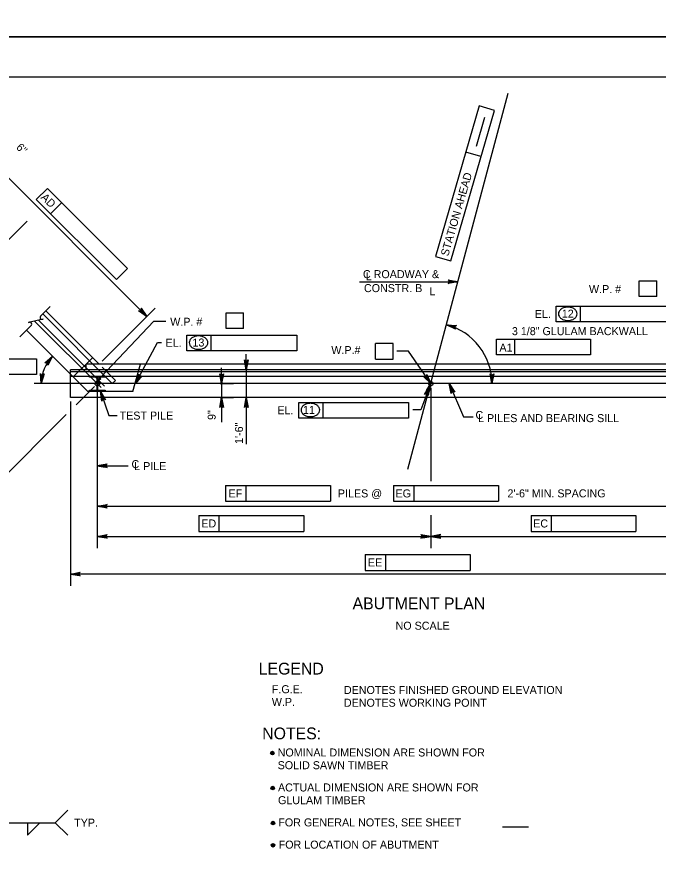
# Model space of a CAD drawing. Extents: x 638304 to 640306, y 296653 to 298435.
# Drawn here: x 639453.1 to 639693.3, y 296941.8 to 297255 of the extents above; entities that cross this region are included whole.
import ezdxf

# ---------------------------------------------------------------- set-up
doc = ezdxf.new("R2010")
doc.units = 0
for name, color, linetype in [('2', 7, 'Continuous'), ('3', 7, 'Continuous'), ('4', 7, 'Continuous'), ('5', 7, 'Continuous'), ('Level 2', 7, 'Continuous'), ('Level 3', 7, 'Continuous'), ('Level 4', 7, 'Continuous'), ('Level 5', 7, 'Continuous'), ('Level 6', 7, 'Continuous'), ('Level 8', 7, 'Continuous'), ('PLT-BNDY', 7, 'Continuous')]:
    doc.layers.add(name, color=color, linetype=linetype)

# ---------------------------------------------------------------- blocks, each defined once
blk = doc.blocks.new('HPILE')
at = {"layer": '3'}
for p, q in [((-0.12, -2.66), (-0.12, 2.66)), ((0.12, 2.66), (0.12, -2.66)), ((-3.67, -3.1), (-0.56, -3.1))]:
    blk.add_line(p, q, dxfattribs=at)
for points in [[(-0.56, 3.1), (-3.67, 3.1), (-3.67, 3.54), (3.67, 3.54), (3.67, 3.1), (0.56, 3.1)], [(0.56, -3.1), (3.67, -3.1), (3.67, -3.54), (-3.67, -3.54), (-3.67, -3.1)]]:
    blk.add_lwpolyline(points, dxfattribs=at)
for centre, start, end in [((-0.56, 2.66), 0, 90), ((0.56, 2.66), 90, 180), ((-0.56, -2.66), 270, 0), ((0.56, -2.66), 180, 270)]:
    blk.add_arc(centre, 0.438, start, end, dxfattribs=at)

msp = doc.modelspace()

# ---------------------------------------------------------------- linework, layer by layer
at = {"layer": '2'}
msp.add_line((639316.46, 297232.46), (640102.46, 297232.46), dxfattribs=at)
at = {"layer": 'Level 2'}
for p, q in [((639483.96, 297124.79), (639464, 297144.75)), ((639479.69, 297114.48), (639456.71, 297137.46)), ((639481.53, 297127.23), (639474.24, 297119.93)), ((639730.06, 297124.79), (639483.96, 297124.79)), ((639496.59, 297114.48), (639499.34, 297124.79)), ((639473.15, 297112.27), (639473.15, 297121.02)), ((639488.84, 297117.43), (639490.06, 297118.64)), ((639496.59, 297114.48), (639479.69, 297114.48)), ((639742.02, 297112.27), (639473.15, 297112.27))]:
    msp.add_line(p, q, dxfattribs=at)
at = {"layer": 'Level 3'}
for p, q in [((639488.84, 297117.43), (639462.79, 297143.54)), ((639473.15, 297121.02), (639473.15, 297122.58)), ((639742.02, 297122.58), (639473.15, 297122.58)), ((639479.08, 297122.58), (639479.08, 297124.79)), ((639483.96, 297124.79), (639479.08, 297124.79)), ((639485.11, 297123.65), (639490.06, 297118.64)), ((639473.15, 297121.93), (639742.02, 297121.93)), ((639473.15, 297120.21), (639742.02, 297120.21)), ((639467.49, 296952.85), (639472.19, 296957.55)), ((639437.91, 296952.85), (639467.49, 296952.85)), ((639457.06, 296952.85), (639457.06, 296948.15)), ((639457.06, 296948.15), (639461.75, 296952.85)), ((639467.49, 296952.85), (639472.19, 296948.15))]:
    msp.add_line(p, q, dxfattribs=at)
msp.add_circle((639608.09, 297117.43), 0.849, dxfattribs=at)
at = {"layer": 'Level 4'}
for p, q in [((639626.25, 297221.5), (639609.92, 297165.05)), ((639615.58, 297163.41), (639631.91, 297219.86)), ((639631.91, 297219.86), (639626.25, 297221.5)), ((639628.25, 297217.17), (639625.11, 297206.31)), ((639626.9, 297202.53), (639621.24, 297204.17)), ((639501.81, 297142.64), (639442.58, 297201.87)), ((639464.55, 297190.63), (639460.38, 297186.46)), ((639464.55, 297190.63), (639494.56, 297160.62)), ((639460.38, 297186.46), (639490.39, 297156.46)), ((639469.89, 297185.3), (639465.72, 297181.13)), ((639443.68, 297165.07), (639456.96, 297178.35)), ((639609.92, 297165.05), (639615.58, 297163.41)), ((639494.56, 297160.62), (639490.39, 297156.46)), ((639581.37, 297155.63), (639618.28, 297155.63)), ((639686.1, 297150.08), (639686.1, 297155.97)), ((639686.1, 297155.97), (639692.68, 297155.97)), ((639692.68, 297150.08), (639692.68, 297155.97)), ((639692.68, 297150.08), (639686.1, 297150.08)), ((639485.05, 297125.88), (639504.94, 297145.77)), ((639531.44, 297144), (639538.02, 297144)), ((639531.44, 297138.1), (639531.44, 297144)), ((639538.02, 297138.1), (639538.02, 297144)), ((639655.04, 297146.46), (639696.17, 297146.46)), ((639655.04, 297140.56), (639655.04, 297146.46)), ((639664.19, 297140.56), (639664.19, 297146.46)), ((639484.65, 297116), (639459.76, 297140.89)), ((639485.87, 297116.52), (639461.18, 297141.21)), ((639538.02, 297138.1), (639531.44, 297138.1)), ((639696.17, 297140.56), (639655.04, 297140.56)), ((639485.05, 297125.88), (639496.73, 297137.56)), ((639516.76, 297135.64), (639557.89, 297135.64)), ((639516.76, 297129.75), (639516.76, 297135.64)), ((639525.91, 297129.75), (639525.91, 297135.64)), ((639557.89, 297135.64), (639557.89, 297129.75)), ((639497.49, 297117.43), (639505.72, 297132.86)), ((639505.72, 297132.86), (639507.31, 297132.86)), ((639593.99, 297132.49), (639587.41, 297132.49)), ((639587.41, 297126.6), (639587.41, 297132.49)), ((639593.99, 297126.6), (639593.99, 297132.49)), ((639632.71, 297134.11), (639667.94, 297134.11)), ((639632.71, 297128.22), (639632.71, 297134.11)), ((639639.54, 297128.22), (639639.54, 297134.11)), ((639667.94, 297134.11), (639667.94, 297128.22)), ((639557.89, 297129.75), (639516.76, 297129.75)), ((639539.02, 297125.53), (639539.02, 297128.48)), ((639425.25, 297126.72), (639460.48, 297126.72)), ((639460.48, 297126.72), (639460.48, 297120.83)), ((639587.41, 297126.6), (639593.99, 297126.6)), ((639667.94, 297128.22), (639632.71, 297128.22)), ((639529.75, 297120.37), (639529.75, 297123.32)), ((639538.45, 297122.58), (639534.6, 297122.58)), ((639539.02, 297122.58), (639539.02, 297112.27)), ((639460.48, 297120.83), (639425.25, 297120.83)), ((639754.22, 297117.43), (639459.61, 297117.43)), ((639482.14, 297116.34), (639475.28, 297109.48)), ((639483.23, 297115.89), (639483.23, 297055.75)), ((639529.25, 297117.43), (639534.17, 297117.43)), ((639529.75, 297117.43), (639529.75, 297112.27)), ((639607.72, 297116.66), (639604.35, 297107.62)), ((639608.09, 297115.89), (639608.09, 297080.88)), ((639473.15, 297110.73), (639473.15, 297041.63)), ((639529.25, 297112.27), (639534.17, 297112.27)), ((639538.45, 297112.27), (639534.6, 297112.27)), ((639558.66, 297110.4), (639599.79, 297110.4)), ((639558.66, 297104.51), (639558.66, 297110.4)), ((639567.81, 297104.51), (639567.81, 297110.4)), ((639599.79, 297110.4), (639599.79, 297104.51)), ((639529.75, 297109.32), (639529.75, 297103.04)), ((639539.02, 297109.32), (639539.02, 297094.76)), ((639604.35, 297107.62), (639601.4, 297107.62)), ((639471.63, 297105.83), (639444.58, 297078.78)), ((639599.79, 297104.51), (639558.66, 297104.51)), ((639483.23, 297086.68), (639494.82, 297086.68)), ((639531.27, 297079.23), (639531.27, 297073.34)), ((639531.27, 297079.23), (639570.57, 297079.23)), ((639538.82, 297079.23), (639538.82, 297073.34)), ((639570.57, 297079.23), (639570.57, 297073.34)), ((639594.17, 297079.23), (639633.46, 297079.23)), ((639594.17, 297079.23), (639594.17, 297073.34)), ((639601.71, 297079.23), (639601.71, 297073.34)), ((639633.46, 297079.23), (639633.46, 297073.34)), ((639531.27, 297073.34), (639570.57, 297073.34)), ((639594.17, 297073.34), (639633.46, 297073.34)), ((639483.23, 297071.48), (639730.79, 297071.48)), ((639521.24, 297067.98), (639560.53, 297067.98)), ((639521.24, 297067.98), (639521.24, 297062.08)), ((639528.78, 297067.98), (639528.78, 297062.08)), ((639560.53, 297067.98), (639560.53, 297062.08)), ((639608.09, 297068.17), (639608.09, 297055.75)), ((639645.63, 297067.98), (639684.92, 297067.98)), ((639645.63, 297067.98), (639645.63, 297062.08)), ((639653.17, 297067.98), (639653.17, 297062.08)), ((639684.92, 297067.98), (639684.92, 297062.08)), ((639483.23, 297060.17), (639605.14, 297060.17)), ((639521.24, 297062.08), (639560.53, 297062.08)), ((639611.04, 297060.17), (639730.79, 297060.17)), ((639645.63, 297062.08), (639684.92, 297062.08)), ((639583.55, 297053.36), (639622.85, 297053.36)), ((639583.55, 297053.36), (639583.55, 297047.46)), ((639591.1, 297053.36), (639591.1, 297047.46)), ((639622.85, 297053.36), (639622.85, 297047.46)), ((639583.55, 297047.46), (639622.85, 297047.46)), ((639742.02, 297046.05), (639473.15, 297046.05)), ((639635.01, 296951.27), (639644.66, 296951.27))]:
    msp.add_line(p, q, dxfattribs=at)
for points in [[(639618.28, 297155.63), (639614.56, 297154.93), (639614.84, 297155.13), (639614.99, 297155.38), (639615.03, 297155.63), (639614.99, 297155.88), (639614.84, 297156.13), (639614.56, 297156.33), (639618.28, 297155.63), (639614.84, 297156.13), (639614.99, 297155.88), (639618.28, 297155.63), (639615.03, 297155.63), (639614.99, 297155.38), (639618.28, 297155.63), (639614.84, 297155.13)], [(639501.81, 297142.64), (639498.68, 297144.78), (639499.03, 297144.72), (639499.31, 297144.79), (639499.52, 297144.94), (639499.66, 297145.14), (639499.73, 297145.43), (639499.67, 297145.77), (639501.81, 297142.64), (639499.73, 297145.43), (639499.66, 297145.14), (639501.81, 297142.64), (639499.52, 297144.94), (639499.31, 297144.79), (639501.81, 297142.64), (639499.03, 297144.72)], [(639482.34, 297117.43), (639504.43, 297140.9), (639508.91, 297140.9)], [(639613.98, 297139.52), (639617.76, 297139.24), (639617.43, 297139.13), (639617.22, 297138.92), (639617.12, 297138.69), (639617.09, 297138.44), (639617.17, 297138.16), (639617.4, 297137.89), (639613.98, 297139.52), (639617.17, 297138.16), (639617.09, 297138.44), (639613.98, 297139.52), (639617.12, 297138.69), (639617.22, 297138.92), (639613.98, 297139.52), (639617.43, 297139.13)], [(639608.09, 297117.43), (639599.79, 297129.63), (639595.34, 297129.63)], [(639466.49, 297127.68), (639464.7, 297124.34), (639464.73, 297124.69), (639464.62, 297124.96), (639464.46, 297125.15), (639464.23, 297125.27), (639463.95, 297125.32), (639463.61, 297125.22), (639466.49, 297127.68), (639463.95, 297125.32), (639464.23, 297125.27), (639466.49, 297127.68), (639464.46, 297125.15), (639464.62, 297124.96), (639466.49, 297127.68), (639464.73, 297124.69)], [(639539.02, 297122.58), (639538.32, 297126.31), (639538.52, 297126.02), (639538.77, 297125.87), (639539.02, 297125.83), (639539.27, 297125.87), (639539.52, 297126.02), (639539.72, 297126.31), (639539.02, 297122.58), (639539.52, 297126.02), (639539.27, 297125.87), (639539.02, 297122.58), (639539.02, 297125.83), (639538.77, 297125.87), (639539.02, 297122.58), (639538.52, 297126.02)], [(639462.25, 297117.43), (639461.94, 297121.2), (639462.11, 297120.89), (639462.35, 297120.72), (639462.59, 297120.65), (639462.84, 297120.67), (639463.11, 297120.79), (639463.33, 297121.05), (639462.25, 297117.43), (639463.11, 297120.79), (639462.84, 297120.67), (639462.25, 297117.43), (639462.59, 297120.65), (639462.35, 297120.72), (639462.25, 297117.43), (639462.11, 297120.89)], [(639497.49, 297117.43), (639498.63, 297121.04), (639498.67, 297120.69), (639498.82, 297120.44), (639499.02, 297120.29), (639499.26, 297120.21), (639499.55, 297120.22), (639499.86, 297120.38), (639497.49, 297117.43), (639499.55, 297120.22), (639499.26, 297120.21), (639497.49, 297117.43), (639499.02, 297120.29), (639498.82, 297120.44), (639497.49, 297117.43), (639498.67, 297120.69)], [(639529.75, 297117.43), (639529.05, 297121.15), (639529.25, 297120.86), (639529.5, 297120.71), (639529.75, 297120.67), (639530, 297120.71), (639530.25, 297120.86), (639530.44, 297121.15), (639529.75, 297117.43), (639530.25, 297120.86), (639530, 297120.71), (639529.75, 297117.43), (639529.75, 297120.67), (639529.5, 297120.71), (639529.75, 297117.43), (639529.25, 297120.86)], [(639608.09, 297117.43), (639605.42, 297120.11), (639605.75, 297119.99), (639606.04, 297120), (639606.27, 297120.11), (639606.45, 297120.28), (639606.57, 297120.55), (639606.57, 297120.89), (639608.09, 297117.43), (639606.57, 297120.55), (639606.45, 297120.28), (639608.09, 297117.43), (639606.27, 297120.11), (639606.04, 297120), (639608.09, 297117.43), (639605.75, 297119.99)], [(639630.99, 297117.43), (639630.29, 297121.15), (639630.49, 297120.86), (639630.74, 297120.71), (639630.99, 297120.67), (639631.24, 297120.71), (639631.49, 297120.86), (639631.69, 297121.15), (639630.99, 297117.43), (639631.49, 297120.86), (639631.24, 297120.71), (639630.99, 297117.43), (639630.99, 297120.67), (639630.74, 297120.71), (639630.99, 297117.43), (639630.49, 297120.86)], [(639607.72, 297116.66), (639607.08, 297112.93), (639606.99, 297113.27), (639606.81, 297113.49), (639606.59, 297113.62), (639606.34, 297113.67), (639606.05, 297113.62), (639605.77, 297113.42), (639607.72, 297116.66), (639606.05, 297113.62), (639606.34, 297113.67), (639607.72, 297116.66), (639606.59, 297113.62), (639606.81, 297113.49), (639607.72, 297116.66), (639606.99, 297113.27)], [(639614.92, 297117.43), (639620.33, 297105), (639624.01, 297105)], [(639614.92, 297117.43), (639617.05, 297114.29), (639616.75, 297114.47), (639616.46, 297114.51), (639616.21, 297114.45), (639616, 297114.31), (639615.83, 297114.08), (639615.77, 297113.73), (639614.92, 297117.43), (639615.83, 297114.08), (639616, 297114.31), (639614.92, 297117.43), (639616.21, 297114.45), (639616.46, 297114.51), (639614.92, 297117.43), (639616.75, 297114.47)], [(639484.41, 297114.65), (639487.5, 297105.55), (639490.72, 297105.55)], [(639484.41, 297114.65), (639486.27, 297111.35), (639485.99, 297111.56), (639485.7, 297111.62), (639485.45, 297111.58), (639485.23, 297111.46), (639485.04, 297111.24), (639484.95, 297110.9), (639484.41, 297114.65), (639485.04, 297111.24), (639485.23, 297111.46), (639484.41, 297114.65), (639485.45, 297111.58), (639485.7, 297111.62), (639484.41, 297114.65), (639485.99, 297111.56)], [(639529.75, 297112.27), (639530.44, 297108.55), (639530.25, 297108.83), (639530, 297108.98), (639529.75, 297109.02), (639529.5, 297108.98), (639529.25, 297108.83), (639529.05, 297108.55), (639529.75, 297112.27), (639529.25, 297108.83), (639529.5, 297108.98), (639529.75, 297112.27), (639529.75, 297109.02), (639530, 297108.98), (639529.75, 297112.27), (639530.25, 297108.83)], [(639539.02, 297112.27), (639539.72, 297108.55), (639539.52, 297108.83), (639539.27, 297108.98), (639539.02, 297109.02), (639538.77, 297108.98), (639538.52, 297108.83), (639538.32, 297108.55), (639539.02, 297112.27), (639538.52, 297108.83), (639538.77, 297108.98), (639539.02, 297112.27), (639539.02, 297109.02), (639539.27, 297108.98), (639539.02, 297112.27), (639539.52, 297108.83)], [(639483.23, 297086.68), (639486.95, 297087.38), (639486.66, 297087.18), (639486.51, 297086.93), (639486.47, 297086.68), (639486.51, 297086.43), (639486.66, 297086.19), (639486.95, 297085.99), (639483.23, 297086.68), (639486.66, 297086.19), (639486.51, 297086.43), (639483.23, 297086.68), (639486.47, 297086.68), (639486.51, 297086.93), (639483.23, 297086.68), (639486.66, 297087.18)], [(639483.23, 297071.48), (639486.95, 297072.18), (639486.66, 297071.98), (639486.51, 297071.73), (639486.47, 297071.48), (639486.51, 297071.23), (639486.66, 297070.98), (639486.95, 297070.78), (639483.23, 297071.48), (639486.66, 297070.98), (639486.51, 297071.23), (639483.23, 297071.48), (639486.47, 297071.48), (639486.51, 297071.73), (639483.23, 297071.48), (639486.66, 297071.98)], [(639483.23, 297060.17), (639486.95, 297060.87), (639486.66, 297060.67), (639486.51, 297060.42), (639486.47, 297060.17), (639486.51, 297059.92), (639486.66, 297059.67), (639486.95, 297059.47), (639483.23, 297060.17), (639486.66, 297059.67), (639486.51, 297059.92), (639483.23, 297060.17), (639486.47, 297060.17), (639486.51, 297060.42), (639483.23, 297060.17), (639486.66, 297060.67)], [(639608.09, 297060.17), (639604.37, 297059.47), (639604.66, 297059.67), (639604.8, 297059.92), (639604.85, 297060.17), (639604.8, 297060.42), (639604.66, 297060.67), (639604.37, 297060.87), (639608.09, 297060.17), (639604.66, 297060.67), (639604.8, 297060.42), (639608.09, 297060.17), (639604.85, 297060.17), (639604.8, 297059.92), (639608.09, 297060.17), (639604.66, 297059.67)], [(639608.09, 297060.17), (639611.81, 297059.47), (639611.53, 297059.67), (639611.38, 297059.92), (639611.33, 297060.17), (639611.38, 297060.42), (639611.53, 297060.67), (639611.81, 297060.87), (639608.09, 297060.17), (639611.53, 297060.67), (639611.38, 297060.42), (639608.09, 297060.17), (639611.33, 297060.17), (639611.38, 297059.92), (639608.09, 297060.17), (639611.53, 297059.67)], [(639473.15, 297046.05), (639476.87, 297046.75), (639476.58, 297046.55), (639476.43, 297046.3), (639476.39, 297046.05), (639476.43, 297045.8), (639476.58, 297045.55), (639476.87, 297045.35), (639473.15, 297046.05), (639476.58, 297045.55), (639476.43, 297045.8), (639473.15, 297046.05), (639476.39, 297046.05), (639476.43, 297046.3), (639473.15, 297046.05), (639476.58, 297046.55)]]:
    msp.add_lwpolyline(points, dxfattribs=at)
for points in [[(639500.07, 297145.07), (639499.38, 297144.38), (639501.81, 297142.64)], [(639538.53, 297125.53), (639539.51, 297125.53), (639539.02, 297122.58)], [(639482.34, 297117.43), (639484.53, 297119.41), (639484.18, 297119.74)], [(639529.26, 297120.37), (639530.24, 297120.37), (639529.75, 297117.43)], [(639608.09, 297117.43), (639606.23, 297119.73), (639606.64, 297120)], [(639607.45, 297114.51), (639606.53, 297114.88), (639608.09, 297117.43)], [(639614.92, 297117.43), (639615.87, 297114.62), (639616.32, 297114.82)], [(639484.41, 297114.65), (639485.12, 297111.78), (639485.59, 297111.94)], [(639529.26, 297109.32), (639530.24, 297109.32), (639529.75, 297112.27)], [(639538.53, 297109.32), (639539.51, 297109.32), (639539.02, 297112.27)], [(639486.17, 297086.19), (639486.17, 297087.17), (639483.23, 297086.68)], [(639486.17, 297071.97), (639486.17, 297070.99), (639483.23, 297071.48)], [(639486.17, 297060.66), (639486.17, 297059.68), (639483.23, 297060.17)], [(639605.14, 297060.66), (639605.14, 297059.68), (639608.09, 297060.17)], [(639611.04, 297060.66), (639611.04, 297059.68), (639608.09, 297060.17)], [(639476.09, 297046.54), (639476.09, 297045.56), (639473.15, 297046.05)]]:
    msp.add_lwpolyline(points, close=True, dxfattribs=at)
for centre, radius in [((639483.23, 297117.43), 0.849), ((639548.78, 296978.97), 0.665), ((639548.78, 296978.97), 0.499), ((639548.78, 296978.97), 0.333), ((639548.78, 296978.97), 0.166), ((639548.91, 296965.87), 0.665), ((639548.91, 296965.87), 0.499), ((639548.91, 296965.87), 0.333), ((639548.91, 296965.87), 0.166), ((639549.03, 296952.76), 0.665), ((639549.03, 296952.76), 0.499), ((639549.03, 296952.76), 0.333), ((639549.03, 296952.76), 0.166), ((639549.03, 296944.4), 0.665), ((639549.03, 296944.4), 0.499), ((639549.03, 296944.4), 0.333), ((639549.03, 296944.4), 0.166)]:
    msp.add_circle(centre, radius, dxfattribs=at)
for centre, radius, start, end in [((639657.74, 297143.62), 1.82, 149.9767, 180), ((639658.54, 297143.15), 2.75, 125.6316, 149.9767), ((639659.07, 297142.42), 3.65, 106.5358, 125.6316), ((639659.41, 297141.26), 4.86, 90, 106.5358), ((639659.41, 297141.26), 4.86, 73.4642, 90), ((639659.75, 297142.42), 3.65, 54.3684, 73.4642), ((639660.28, 297143.15), 2.75, 30.0233, 54.3684), ((639661.08, 297143.62), 1.82, 0, 30.0233), ((639657.74, 297143.62), 1.82, 180, 210.0233), ((639658.54, 297144.08), 2.75, 210.0233, 234.3684), ((639659.07, 297144.81), 3.65, 234.3684, 253.4642), ((639659.41, 297145.97), 4.86, 253.4642, 270), ((639659.41, 297145.97), 4.86, 270, 286.5358), ((639659.75, 297144.81), 3.65, 286.5358, 305.6316), ((639660.28, 297144.08), 2.75, 305.6316, 329.9767), ((639661.08, 297143.62), 1.82, 329.9767, 0), ((639608.13, 297117.43), 22.86, 359.9991, 75.1778), ((639520.26, 297132.34), 2.75, 125.6316, 149.9767), ((639520.79, 297131.61), 3.65, 106.5358, 125.6316), ((639521.13, 297130.45), 4.86, 90, 106.5358), ((639521.13, 297130.45), 4.86, 73.4642, 90), ((639521.47, 297131.61), 3.65, 54.3684, 73.4642), ((639522, 297132.34), 2.75, 30.0233, 54.3684), ((639519.46, 297132.8), 1.82, 149.9767, 180), ((639519.46, 297132.8), 1.82, 180, 210.0233), ((639520.26, 297133.27), 2.75, 210.0233, 234.3684), ((639522, 297133.27), 2.75, 305.6316, 329.9767), ((639522.8, 297132.8), 1.82, 0, 30.0233), ((639522.8, 297132.8), 1.82, 329.9767, 0), ((639520.79, 297134), 3.65, 234.3684, 253.4642), ((639521.13, 297135.16), 4.86, 253.4642, 270), ((639521.13, 297135.16), 4.86, 270, 286.5358), ((639521.47, 297134), 3.65, 286.5358, 305.6316), ((639476.74, 297117.43), 14.5, 134.9989, 180.0015), ((639562.68, 297106.36), 3.65, 106.5358, 125.6316), ((639563.03, 297105.2), 4.86, 90, 106.5358), ((639563.03, 297105.2), 4.86, 73.4642, 90), ((639563.37, 297106.36), 3.65, 54.3684, 73.4642), ((639561.35, 297107.56), 1.82, 149.9767, 180), ((639561.35, 297107.56), 1.82, 180, 210.0233), ((639562.16, 297107.1), 2.75, 125.6316, 149.9767), ((639562.16, 297108.02), 2.75, 210.0233, 234.3684), ((639563.89, 297107.1), 2.75, 30.0233, 54.3684), ((639563.89, 297108.02), 2.75, 305.6316, 329.9767), ((639564.7, 297107.56), 1.82, 0, 30.0233), ((639564.7, 297107.56), 1.82, 329.9767, 0), ((639562.68, 297108.76), 3.65, 234.3684, 253.4642), ((639563.03, 297109.92), 4.86, 253.4642, 270), ((639563.03, 297109.92), 4.86, 270, 286.5358), ((639563.37, 297108.76), 3.65, 286.5358, 305.6316)]:
    msp.add_arc(centre, radius, start, end, dxfattribs=at)
at = {"layer": 'Level 6'}
msp.add_line((639599.54, 297085.36), (639637.1, 297226.24), dxfattribs=at)
at = {"layer": 'Level 8'}
for p, q in [((639465.56, 297146.32), (639461.99, 297142.74)), ((639458.56, 297139.31), (639454.25, 297135))]:
    msp.add_line(p, q, dxfattribs=at)
msp.add_lwpolyline([(639462.67, 297141.55), (639463.01, 297141.63), (639457.48, 297140.37), (639457.85, 297140.45)], dxfattribs=at)
for centre, start, end in [((639462.49, 297142.24), 135, 285), ((639458.01, 297139.76), 320.3286, 102.8672)]:
    msp.add_arc(centre, 0.709, start, end, dxfattribs=at)
at = {"layer": 'PLT-BNDY'}
for points in [[(639276.46, 297841.46), (640117.46, 297841.46), (640117.46, 297247.46), (639276.46, 297247.46)], [(639276.46, 297247.46), (640117.46, 297247.46), (640117.46, 296653.46), (639276.46, 296653.46)]]:
    msp.add_lwpolyline(points, close=True, dxfattribs=at)

# ---------------------------------------------------------------- block references
at = {"layer": 'Level 3', "xscale": 0.7859001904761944, "yscale": 0.7859001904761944}
msp.add_blockref('HPILE', (639483.23, 297117.43), dxfattribs=at)

# ---------------------------------------------------------------- texts
at = {"layer": '4'}
for s, height, p in [('ABUTMENT PLAN', 4.4294, (639578.81, 297032.86)), ('NO SCALE', 3, (639594.91, 297025.21)), ('NOTES:', 4.429, (639544.98, 296984.13))]:
    msp.add_text(s, height=height, dxfattribs=at).set_placement(p)
at = {"layer": '5'}
msp.add_text('LEGEND', height=4.429, dxfattribs=at).set_placement((639543.67, 297008.41))
at = {"layer": 'Level 4'}
for s, height, rotation, p in [('STATION AHEAD', 3.0001, 73.8664, (639614.62, 297165)), ('AD', 3, 314.9382, (639461.89, 297187.01))]:
    msp.add_text(s, height=height, rotation=rotation, dxfattribs=at).set_placement(p)
for s, height, p in [('C ROADWAY &', 3.0001, (639582.69, 297156.97)), ('L', 3, (639583.71, 297156.15)), ('CONSTR. B', 3, (639583.08, 297151.74)), ('L', 3, (639607.59, 297150.59)), ('W.P. #', 3, (639667.33, 297151.37)), ('EL.', 3, (639647.03, 297142.04)), ('12', 3, (639657.16, 297142.16)), ('W.P. # ', 3, (639510.53, 297139.13)), ('EL.', 3, (639508.76, 297131.23)), ('13', 3, (639518.86, 297131.34)), ('W.P.#', 3, (639570.85, 297128.52)), ('A1', 3, (639633.8, 297129.43)), ('TEST PILE', 3, (639491.58, 297103.96)), ('EL.', 3, (639550.65, 297105.99)), ('11', 3, (639560.23, 297106.1)), ('C', 3, (639624.84, 297104.19)), ('L PILES AND BEARING SILL', 3.0001, (639625.8, 297103.01)), ('C', 3, (639496.03, 297085.76)), ('L PILE', 3, (639497.05, 297085.03)), ('EF', 3, (639532.38, 297074.79)), ('PILES @', 3, (639573.32, 297074.79)), ('EG', 3, (639594.89, 297074.79)), ('2\'-6" MIN. SPACING', 3.0001, (639636.81, 297074.81)), ('ED', 3, (639522.17, 297063.53)), ('EC', 3, (639646.44, 297063.53)), ('EE', 3, (639584.55, 297048.91)), ('NOMINAL DIMENSION ARE SHOWN FOR ', 3.0001, (639550.76, 296977.7)), ('SOLID SAWN TIMBER', 3.0001, (639550.76, 296972.93)), ('ACTUAL DIMENSION ARE SHOWN FOR ', 3.0001, (639550.89, 296964.59)), ('GLULAM TIMBER', 3.0001, (639550.89, 296959.82)), ('TYP.', 3, (639474.57, 296951.39)), ('FOR GENERAL NOTES, SEE SHEET    ', 3.0001, (639551.01, 296951.49)), ('FOR LOCATION OF ABUTMENT', 3.0001, (639551.14, 296943.16))]:
    msp.add_text(s, height=height, dxfattribs=at).set_placement(p)
at = {"layer": 'Level 5'}
for s, rotation, p in [('6"', 315, (639452.62, 297205.75)), ('9"', 90, (639527.57, 297103.82)), ('1\'-6"', 90, (639537.78, 297094.84))]:
    msp.add_text(s, height=3, rotation=rotation, dxfattribs=at).set_placement(p)
for s, height, p in [('3 1/8" GLULAM BACKWALL', 3.0001, (639638.47, 297135.61)), ('F.G.E.', 3, (639548.58, 297001.41)), ('DENOTES FINISHED GROUND ELEVATION', 3.0001, (639575.57, 297001.12)), ('W.P.', 3, (639548.58, 296996.64)), ('DENOTES WORKING POINT', 3.0001, (639575.57, 296996.34))]:
    msp.add_text(s, height=height, dxfattribs=at).set_placement(p)

doc.saveas('drawing.dxf')
